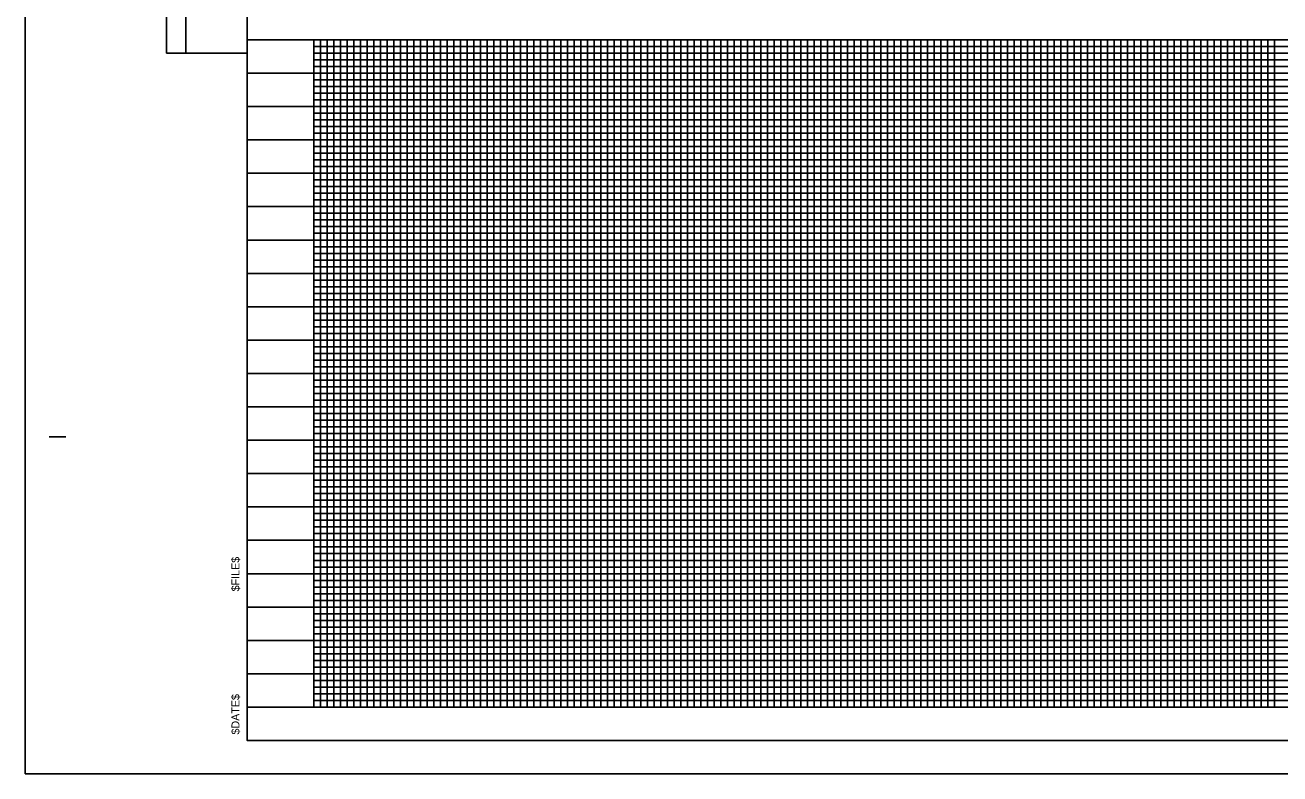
# Model space of a CAD drawing. Extents: x 2431000 to 2534000, y 645879 to 714000.
# Drawn here: x 2466807 to 2467748, y 668842 to 669403 of the extents above; entities that cross this region are included whole.
import ezdxf

# ---------------------------------------------------------------- set-up
doc = ezdxf.new("R2010")
doc.units = 0
for name, color, linetype in [('Prop Dimension', 7, 'Continuous'), ('Prop Dimension Text', 7, 'Continuous'), ('Prop Shade Light', 7, 'Continuous'), ('Prop Shade Medium', 7, 'Continuous'), ('Sheet Cross Section CELL', 7, 'Continuous'), ('Sheet Cross Section Grid Major CELL', 7, 'Continuous'), ('Sheet North Arrow Point CELL', 7, 'Continuous'), ('Sheet Plan And Profile CELL', 7, 'Continuous')]:
    doc.layers.add(name, color=color, linetype=linetype)

msp = doc.modelspace()

# ---------------------------------------------------------------- linework, layer by layer
at = {"layer": 'Prop Dimension'}
msp.add_lwpolyline([(2466807.25, 668842.06), (2468490.75, 668842.06), (2468490.75, 669942.06), (2466807.25, 669942.06)], close=True, dxfattribs=at)
at = {"layer": 'Prop Shade Light'}
for p, q in [((2466913.23, 669382.06), (2466913.23, 669872.71)), ((2466927.77, 669382.06), (2466927.77, 669872.72)), ((2466973.77, 669382.06), (2466913.23, 669382.06))]:
    msp.add_line(p, q, dxfattribs=at)
at = {"layer": 'Prop Shade Medium'}
msp.add_line((2466973.75, 668892.06), (2466973.75, 669392.06), dxfattribs=at)
at = {"layer": 'Sheet Cross Section CELL'}
for p, q in [((2467023.75, 669387.06), (2468423.75, 669387.06)), ((2468423.75, 669382.06), (2467023.75, 669382.06)), ((2467023.75, 669377.06), (2468423.75, 669377.06)), ((2468423.75, 669372.06), (2467023.75, 669372.06)), ((2467023.75, 669362.06), (2468423.75, 669362.06)), ((2468423.75, 669357.06), (2467023.75, 669357.06)), ((2467023.75, 669352.06), (2468423.75, 669352.06)), ((2468423.75, 669347.06), (2467023.75, 669347.06)), ((2467023.75, 669337.06), (2468423.75, 669337.06)), ((2468423.75, 669332.06), (2467023.75, 669332.06)), ((2467023.75, 669327.06), (2468423.75, 669327.06)), ((2468423.75, 669322.06), (2467023.75, 669322.06)), ((2467023.75, 669312.06), (2468423.75, 669312.06)), ((2468423.75, 669307.06), (2467023.75, 669307.06)), ((2467023.75, 669302.06), (2468423.75, 669302.06)), ((2468423.75, 669297.06), (2467023.75, 669297.06)), ((2467023.75, 669287.06), (2468423.75, 669287.06)), ((2468423.75, 669282.06), (2467023.75, 669282.06)), ((2467023.75, 669277.06), (2468423.75, 669277.06)), ((2468423.75, 669272.06), (2467023.75, 669272.06)), ((2467023.75, 669262.06), (2468423.75, 669262.06)), ((2468423.75, 669257.06), (2467023.75, 669257.06)), ((2467023.75, 669252.06), (2468423.75, 669252.06)), ((2468423.75, 669247.06), (2467023.75, 669247.06)), ((2467023.75, 669237.06), (2468423.75, 669237.06)), ((2468423.75, 669232.06), (2467023.75, 669232.06)), ((2467023.75, 669227.06), (2468423.75, 669227.06)), ((2468423.75, 669222.06), (2467023.75, 669222.06)), ((2467023.75, 669212.06), (2468423.75, 669212.06)), ((2468423.75, 669207.06), (2467023.75, 669207.06)), ((2467023.75, 669202.06), (2468423.75, 669202.06)), ((2468423.75, 669197.06), (2467023.75, 669197.21)), ((2467023.75, 669187.06), (2468423.75, 669187.06)), ((2468423.75, 669182.06), (2467023.75, 669182.06)), ((2467023.75, 669177.06), (2468423.75, 669177.06)), ((2468423.75, 669172.06), (2467023.75, 669172.06)), ((2467023.75, 669162.06), (2468423.75, 669162.06)), ((2468423.75, 669157.06), (2467023.75, 669157.06)), ((2467023.75, 669152.06), (2468423.75, 669152.06)), ((2468423.75, 669147.06), (2467023.75, 669147.06)), ((2467023.75, 669137.06), (2468423.75, 669137.06)), ((2468423.75, 669132.06), (2467023.75, 669132.06)), ((2467023.75, 669127.06), (2468423.75, 669127.06)), ((2468423.75, 669122.06), (2467023.75, 669122.06)), ((2467023.75, 669112.06), (2468423.75, 669112.06)), ((2468423.75, 669107.06), (2467023.75, 669107.06)), ((2467023.75, 669102.06), (2468423.75, 669102.06)), ((2468423.75, 669097.06), (2467023.75, 669097.06)), ((2467023.75, 669087.06), (2468423.75, 669087.06)), ((2468423.75, 669082.06), (2467023.75, 669082.06)), ((2467023.75, 669077.06), (2468423.75, 669077.06)), ((2468423.75, 669072.06), (2467023.75, 669072.06)), ((2467023.75, 669062.06), (2468423.75, 669062.06)), ((2468423.75, 669057.06), (2467023.75, 669057.06)), ((2467023.75, 669052.06), (2468423.75, 669052.06)), ((2468423.75, 669047.06), (2467023.75, 669047.06)), ((2467023.75, 669037.06), (2468423.75, 669037.06)), ((2468423.75, 669032.06), (2467023.75, 669032.06)), ((2467023.75, 669027.06), (2468423.75, 669027.06)), ((2468423.75, 669022.06), (2467023.75, 669022.06)), ((2467023.75, 669012.06), (2468423.75, 669012.06)), ((2468423.75, 669007.06), (2467023.75, 669007.06)), ((2467023.75, 669002.06), (2468423.75, 669002.06)), ((2468423.75, 668997.06), (2467023.75, 668997.06)), ((2467023.75, 668987.06), (2468423.75, 668987.06)), ((2468423.75, 668982.06), (2467023.75, 668982.06)), ((2467023.75, 668977.06), (2468423.75, 668977.06)), ((2468423.75, 668972.06), (2467023.75, 668972.06)), ((2467023.75, 668962.06), (2468423.75, 668962.06)), ((2468423.75, 668957.06), (2467023.75, 668957.06)), ((2467023.75, 668952.06), (2468423.75, 668952.06)), ((2468423.75, 668947.06), (2467023.75, 668947.06)), ((2467023.75, 668937.06), (2468423.75, 668937.06)), ((2468423.75, 668932.06), (2467023.75, 668932.06)), ((2467023.75, 668927.06), (2468423.75, 668927.06)), ((2468423.75, 668922.06), (2467023.75, 668922.06)), ((2467023.75, 668912.06), (2468423.75, 668912.06)), ((2468423.75, 668907.06), (2467023.75, 668907.06)), ((2467023.75, 668902.06), (2468423.75, 668902.06)), ((2467023.75, 668897.06), (2468423.75, 668897.06))]:
    msp.add_line(p, q, dxfattribs=at)
for points in [[(2467003.75, 669392.06), (2467008.75, 669392.06), (2467013.75, 669392.06), (2467018.75, 669392.06), (2467028.75, 669392.06), (2467028.75, 668892.06), (2467033.75, 668892.06), (2467033.75, 669392.06), (2467038.75, 669392.06), (2467038.75, 668892.06), (2467043.75, 668892.06), (2467043.75, 669392.06), (2467053.75, 669392.06), (2467053.75, 668892.06), (2467058.75, 668892.06), (2467058.75, 669392.06), (2467063.75, 669392.06), (2467063.75, 668892.06), (2467068.75, 668892.06), (2467078.75, 668892.06), (2467083.75, 668892.06), (2467083.75, 669392.06), (2467088.75, 669392.06), (2467088.75, 668892.06), (2467093.75, 668892.06), (2467093.75, 669392.06), (2467103.75, 669392.06), (2467103.75, 668892.06), (2467108.75, 668892.06), (2467108.75, 669392.06), (2467113.75, 669392.06), (2467113.75, 668892.06), (2467118.75, 668892.06), (2467118.75, 669392.06), (2467128.75, 669392.06), (2467128.75, 668892.06), (2467133.75, 668892.06), (2467133.75, 669392.06), (2467138.75, 669392.06), (2467138.75, 668892.06), (2467143.75, 668892.06), (2467143.75, 669392.06), (2467153.75, 669392.06), (2467153.75, 668892.06), (2467158.75, 668892.06), (2467158.75, 669392.06), (2467163.75, 669392.06), (2467163.75, 668892.06), (2467168.75, 668892.06), (2467168.75, 669392.06), (2467178.75, 669392.06), (2467178.75, 668892.06), (2467183.75, 668892.06), (2467183.75, 669392.06), (2467188.75, 669392.06), (2467188.75, 668892.06), (2467193.75, 668892.06), (2467193.75, 669392.06), (2467203.75, 669392.06), (2467203.75, 668892.06), (2467208.75, 668892.06), (2467208.75, 669392.06), (2467213.75, 669392.06), (2467213.75, 668892.06), (2467218.75, 668892.06), (2467218.75, 669392.06), (2467228.75, 669392.06), (2467228.75, 668892.06), (2467233.75, 668892.06), (2467233.75, 669392.06), (2467238.75, 669392.06), (2467238.75, 668892.06)], [(2467068.75, 668892.06), (2467068.75, 669392.06), (2467078.75, 669392.06), (2467078.75, 668892.06)], [(2467238.75, 668892.06), (2467243.75, 668892.06), (2467243.75, 669392.06), (2467253.75, 669392.06), (2467253.75, 668892.06), (2467258.75, 668892.06), (2467258.75, 669392.06), (2467263.75, 669392.06), (2467263.75, 668892.06), (2467268.75, 668892.06), (2467268.75, 669392.06), (2467278.75, 669392.06), (2467278.75, 668892.06), (2467283.75, 668892.06), (2467283.75, 669392.06), (2467288.75, 669392.06), (2467288.75, 668892.06), (2467293.75, 668892.06), (2467293.75, 669392.06), (2467303.75, 669392.06), (2467303.75, 668892.06), (2467308.75, 668892.06), (2467308.75, 669392.06), (2467313.75, 669392.06), (2467313.75, 668892.06), (2467318.75, 668892.06), (2467318.75, 669392.06), (2467328.75, 669392.06), (2467328.75, 668892.06), (2467333.75, 668892.06), (2467333.75, 669392.06), (2467338.75, 669392.06), (2467338.75, 668892.06), (2467343.75, 668892.06), (2467343.75, 669392.06), (2467353.75, 669392.06), (2467353.75, 668892.06), (2467358.75, 668892.06), (2467358.75, 669392.06), (2467363.75, 669392.06), (2467363.75, 668892.06), (2467368.75, 668892.06), (2467368.75, 669392.06), (2467378.75, 669392.06), (2467378.75, 668892.06), (2467383.75, 668892.06), (2467383.75, 669392.06), (2467388.75, 669392.06), (2467388.75, 668892.06), (2467393.75, 668892.06), (2467393.75, 669392.06), (2467403.75, 669392.06), (2467403.75, 668892.06), (2467408.75, 668892.06), (2467408.75, 669392.06), (2467413.75, 669392.06), (2467413.75, 668892.06), (2467418.75, 668892.06), (2467418.75, 669392.06), (2467428.75, 669392.06), (2467428.75, 668892.06), (2467433.75, 668892.06), (2467433.75, 669392.06), (2467438.75, 669392.06), (2467438.75, 668892.06), (2467443.75, 668892.06), (2467443.75, 669392.06), (2467453.75, 669392.06), (2467453.75, 668892.06), (2467458.75, 668892.06), (2467458.75, 669392.06), (2467463.75, 669392.06), (2467463.75, 668892.06), (2467468.75, 668892.06), (2467468.75, 669392.06), (2467478.75, 669392.06), (2467478.75, 668892.06), (2467483.75, 668892.06), (2467483.75, 669392.06), (2467488.75, 669392.06), (2467488.75, 668892.06), (2467493.75, 668892.06), (2467493.75, 669392.06), (2467503.75, 669392.06), (2467503.75, 668892.06), (2467508.75, 668892.06), (2467508.75, 669392.06), (2467513.75, 669392.06), (2467513.75, 668892.06), (2467518.75, 668892.06), (2467518.75, 669392.06), (2467528.75, 669392.06), (2467528.75, 668892.06), (2467533.75, 668892.06), (2467533.75, 669392.06), (2467538.75, 669392.06), (2467538.75, 668892.06), (2467543.75, 668892.06), (2467543.75, 669392.06), (2467553.75, 669392.06)], [(2467553.75, 669392.06), (2467553.75, 668892.06), (2467558.75, 668892.06), (2467558.75, 669392.06), (2467563.75, 669392.06), (2467563.75, 668892.06), (2467568.75, 668892.06), (2467568.75, 669392.06), (2467578.75, 669392.06), (2467578.75, 668892.06), (2467583.75, 668892.06), (2467583.75, 669392.06), (2467588.75, 669392.06), (2467588.75, 668892.06), (2467593.75, 668892.06), (2467593.75, 669392.06), (2467603.75, 669392.06), (2467603.75, 668892.06), (2467608.75, 668892.06), (2467608.75, 669392.06), (2467613.75, 669392.06), (2467613.75, 668892.06), (2467618.75, 668892.06), (2467618.75, 669392.06), (2467628.75, 669392.06), (2467628.75, 668892.06), (2467633.75, 668892.06), (2467633.75, 669392.06), (2467638.75, 669392.06), (2467638.75, 668892.06), (2467643.75, 668892.06), (2467643.75, 669392.06), (2467653.75, 669392.06), (2467653.75, 668892.06), (2467658.75, 668892.06), (2467658.75, 669392.06), (2467663.75, 669392.06), (2467663.75, 668892.06), (2467668.75, 668892.06), (2467668.75, 669392.06), (2467678.75, 669392.06), (2467678.75, 668892.06), (2467678.75, 668892.06), (2467683.75, 668892.06), (2467683.75, 669392.06), (2467688.75, 669392.06), (2467688.75, 668892.06), (2467693.75, 668892.06), (2467693.75, 669392.06), (2467703.75, 669392.06), (2467703.75, 668892.06), (2467708.75, 668892.06), (2467708.75, 669392.06), (2467713.75, 669392.06), (2467713.75, 668892.06), (2467718.75, 668892.06), (2467718.75, 669392.06), (2467728.75, 669392.06), (2467728.75, 668892.06), (2467733.75, 668892.06), (2467733.75, 669392.06), (2467738.75, 669392.06), (2467738.75, 668892.06), (2467743.75, 668892.06), (2467743.75, 669392.06), (2467753.75, 669392.06)]]:
    msp.add_lwpolyline(points, dxfattribs=at)
at = {"layer": 'Sheet Cross Section Grid Major CELL'}
for points in [[(2466998.75, 669392.06), (2467048.75, 669392.06), (2467048.75, 668892.06), (2467098.75, 668892.06), (2467098.75, 669392.06), (2467148.75, 669392.06), (2467148.75, 668892.06), (2467198.75, 668892.06), (2467198.75, 669392.06), (2467248.75, 669392.06), (2467248.75, 668892.06), (2467298.75, 668892.06), (2467298.75, 669392.06), (2467348.75, 669392.06), (2467348.75, 668892.06), (2467398.75, 668892.06), (2467398.75, 669392.06), (2467448.75, 669392.06), (2467448.75, 668892.06), (2467498.75, 668892.06), (2467498.75, 669392.06), (2467548.75, 669392.06), (2467548.75, 668892.06), (2467598.75, 668892.06), (2467598.75, 668892.06), (2467598.75, 669392.06), (2467648.75, 669392.06), (2467648.75, 668892.06), (2467698.75, 668892.06), (2467698.75, 669392.06), (2467748.75, 669392.06)], [(2466973.75, 669367.06), (2468473.75, 669367.06)], [(2468473.75, 669317.06), (2466973.75, 669317.06), (2466973.75, 669267.06), (2468473.75, 669267.06)], [(2468473.75, 669217.06), (2466973.75, 669217.06), (2466973.75, 669167.06), (2468473.75, 669167.06)], [(2468473.75, 669117.06), (2466973.75, 669117.06), (2466973.75, 669067.06), (2468473.75, 669067.06)], [(2468473.75, 669017.06), (2466973.75, 669017.06), (2466973.75, 668967.06), (2468473.75, 668967.06)], [(2468473.75, 668917.06), (2466973.75, 668917.06)]]:
    msp.add_lwpolyline(points, dxfattribs=at)
at = {"layer": 'Sheet North Arrow Point CELL'}
for p, q in [((2467473.75, 669392.06), (2467523.75, 669392.06)), ((2467573.75, 669392.06), (2467623.75, 669392.06)), ((2467673.75, 669392.06), (2467723.75, 669392.06)), ((2466973.75, 668892.06), (2466973.75, 668892.06))]:
    msp.add_line(p, q, dxfattribs=at)
for points in [[(2467023.75, 669392.06), (2467023.75, 668892.06), (2467073.75, 668892.06), (2467073.75, 669392.06), (2467123.75, 669392.06), (2467123.75, 668892.06), (2467173.75, 668892.06), (2467173.75, 669392.06), (2467223.75, 669392.06), (2467223.75, 668892.06), (2467273.75, 668892.06), (2467273.75, 669392.06), (2467323.75, 669392.06), (2467323.75, 668892.06), (2467373.75, 668892.06), (2467373.75, 669392.06), (2467423.75, 669392.06), (2467423.75, 668892.06), (2467473.75, 668892.06), (2467473.75, 669392.06), (2467523.75, 669392.06), (2467523.75, 668892.06), (2467573.75, 668892.06), (2467573.75, 669392.06), (2467623.75, 669392.06), (2467623.75, 668892.06), (2467673.75, 668892.06), (2467673.75, 669392.06), (2467723.75, 669392.06), (2467723.75, 668892.06), (2467773.75, 668892.06)], [(2468473.75, 669342.06), (2466973.75, 669342.06)], [(2468473.75, 669292.06), (2466973.75, 669292.06), (2466973.75, 669242.06), (2468473.75, 669242.06)], [(2468473.75, 669192.06), (2466973.75, 669192.06), (2466973.75, 669142.06), (2468473.75, 669142.06)], [(2468473.75, 669092.06), (2466973.75, 669092.06), (2466973.75, 669042.06), (2468473.75, 669042.06)], [(2468473.75, 668992.06), (2466973.75, 668992.06), (2466973.75, 668992.06), (2466973.75, 668942.06), (2468473.75, 668942.06)], [(2468473.75, 668892.06), (2466973.75, 668892.06)], [(2468473.75, 668892.06), (2466973.75, 668892.06)]]:
    msp.add_lwpolyline(points, dxfattribs=at)
at = {"layer": 'Sheet Plan And Profile CELL'}
for p, q in [((2466973.75, 669392.06), (2468473.75, 669392.06)), ((2466825.25, 669094.56), (2466837.75, 669094.56)), ((2468473.75, 668892.06), (2466973.75, 668892.06)), ((2468473.75, 668892.06), (2466973.75, 668892.06)), ((2466973.75, 668867.06), (2468473.75, 668867.06)), ((2466973.75, 668867.06), (2466973.75, 668867.06)), ((2466973.75, 668867.06), (2466973.75, 668867.06)), ((2466973.75, 668867.06), (2466973.75, 668867.06)), ((2466973.75, 668867.06), (2466973.75, 668867.06)), ((2466973.75, 668867.06), (2466973.75, 668867.06)), ((2466973.75, 668867.06), (2466973.75, 668867.06)), ((2466973.75, 668867.06), (2466973.75, 668867.06))]:
    msp.add_line(p, q, dxfattribs=at)
msp.add_lwpolyline([(2468473.75, 669917.06), (2466973.75, 669917.06), (2466973.75, 668867.06), (2468473.75, 668867.06)], close=True, dxfattribs=at)
msp.add_lwpolyline([(2467011.25, 668867.06), (2467011.25, 668867.06)], dxfattribs=at)

# ---------------------------------------------------------------- texts
at = {"layer": 'Prop Dimension Text'}
for s, p in [('$FILE$', (2466967.96, 668978.82)), ('$DATE$', (2466967.96, 668871.54))]:
    msp.add_text(s, height=6, rotation=90, dxfattribs=at).set_placement(p)

doc.saveas('drawing.dxf')
